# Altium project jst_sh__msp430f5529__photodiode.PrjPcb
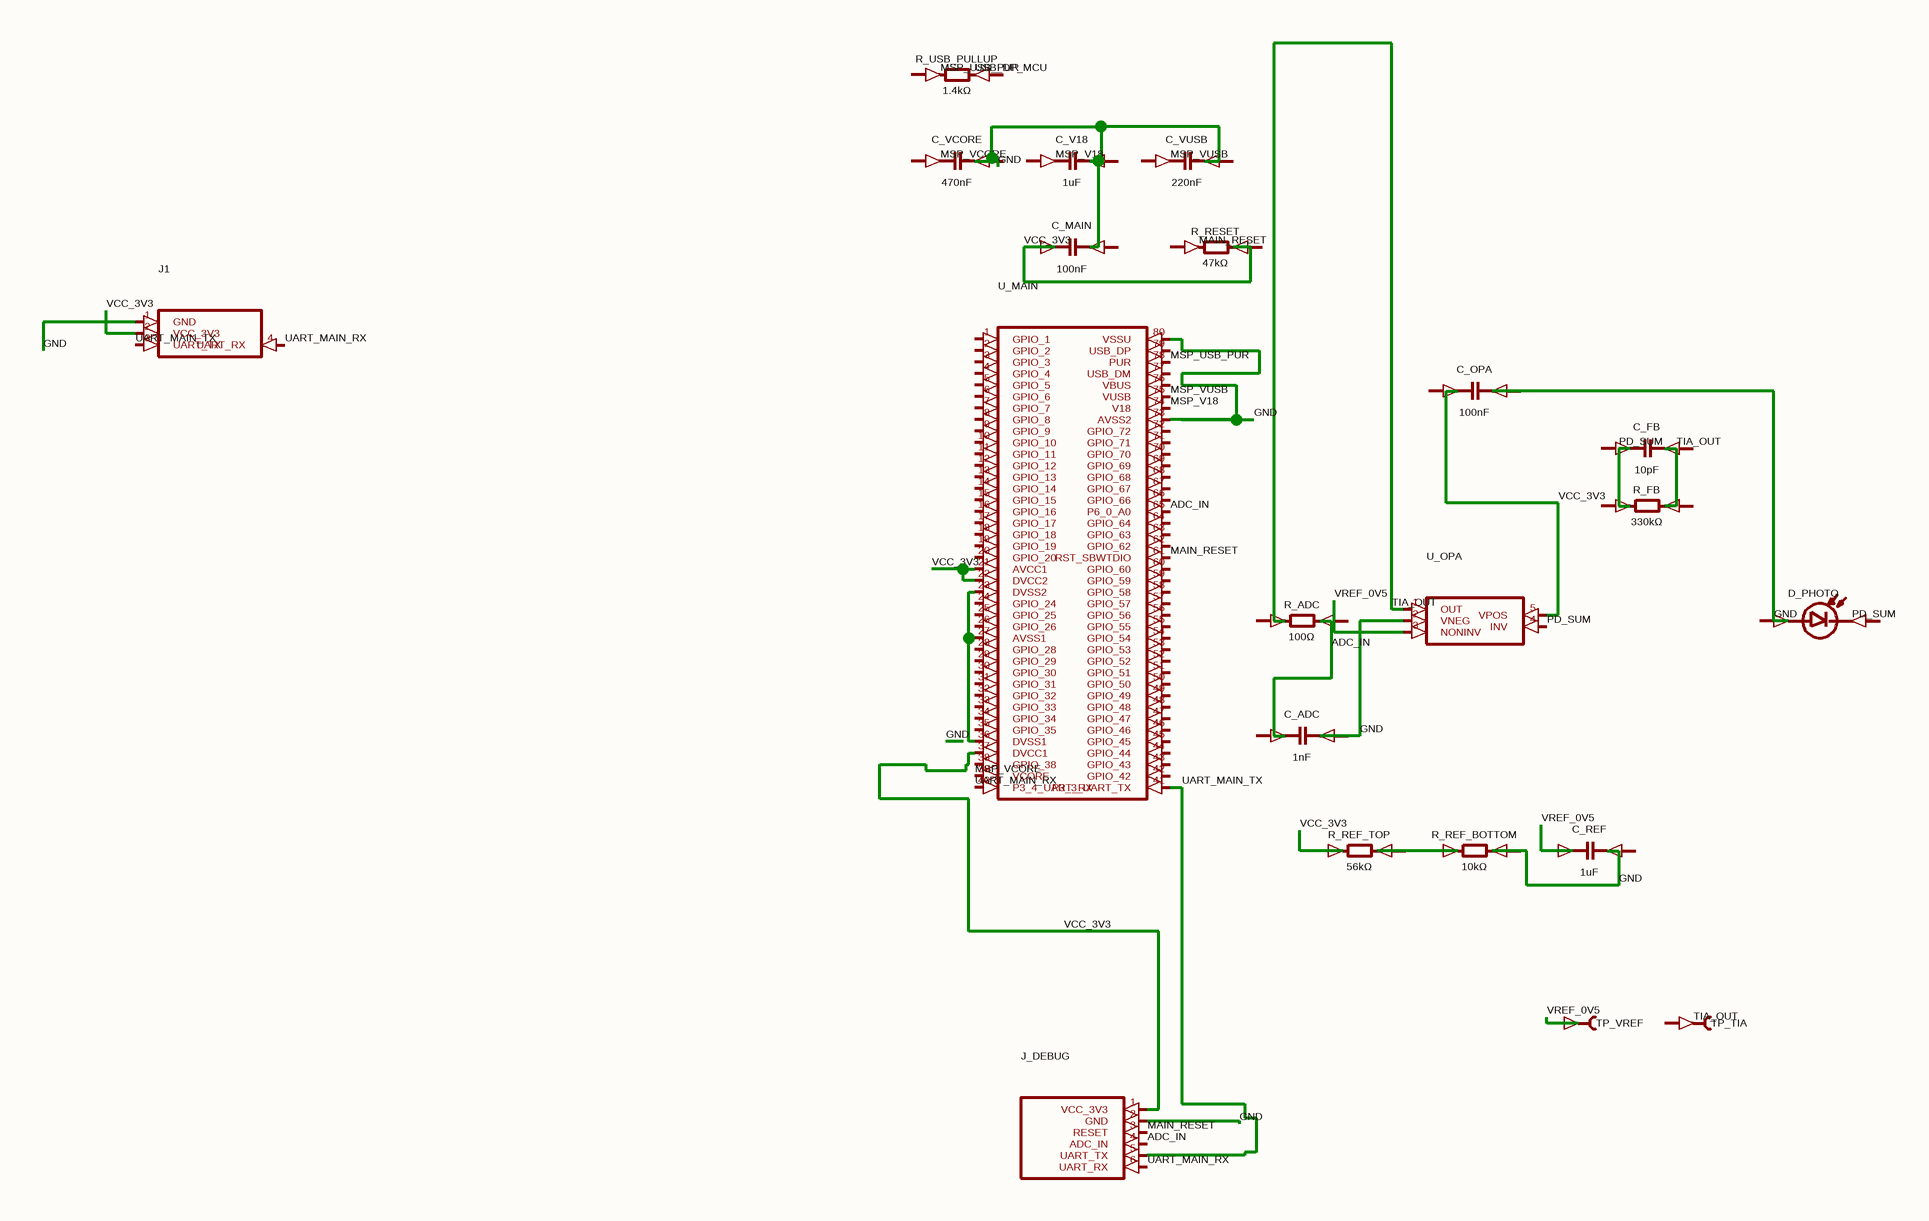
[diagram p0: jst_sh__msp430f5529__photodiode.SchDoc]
1 sheet, 21 parts. Net scope: global (net labels, ports and power ports of the same name join across sheets).
Board file: jst_sh__msp430f5529__photodiode.PcbDoc

## Sheet jst_sh__msp430f5529__photodiode.SchDoc
size 212 x 150 mm

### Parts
C_ADC  1nF
C_FB  10pF
C_MAIN  100nF
C_OPA  100nF
C_REF  1uF
C_V18  1uF
C_VCORE  470nF
C_VUSB  220nF
D_PHOTO  (no value)
J1  (no value)
J_DEBUG  (no value)
R_ADC  100Ω
R_FB  330kΩ
R_REF_BOTTOM  10kΩ
R_REF_TOP  56kΩ
R_RESET  47kΩ
R_USB_PULLUP  1.4kΩ
TP_TIA  (no value)
TP_VREF  (no value)
U_MAIN  (no value)
U_OPA  (no value)

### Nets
ADC_IN: J_DEBUG.4(ADC_IN) U_MAIN.65(P6_0_A0)
GND: C_ADC.2(neg) C_OPA.2(neg) C_REF.1(pos) J1.1(GND) J_DEBUG.2(GND) R_REF_BOTTOM.2(cathode) TP_VREF.1(pin1) U_MAIN.73(AVSS2) U_MAIN.80(VSSU) U_OPA.2(VNEG) U_OPA.3(NONINV)  [also labelled VREF_0V5]
MAIN_RESET: J_DEBUG.3(RESET) U_MAIN.61(RST_SBWTDIO)
MSP_USB_PUR: U_MAIN.78(PUR)
MSP_V18: U_MAIN.74(V18)
MSP_VCORE: U_MAIN.39(VCORE)
MSP_VUSB: U_MAIN.75(VUSB)
PD_SUM: U_OPA.4(INV)
TIA_OUT: U_OPA.1(OUT)
UART_MAIN_RX: J1.4(UART_RX) J_DEBUG.6(UART_RX) U_MAIN.40(P3_4_UART_RX)
UART_MAIN_TX: J1.3(UART_TX) J_DEBUG.5(UART_TX) U_MAIN.41(P3_3_UART_TX)
VCC_3V3: C_MAIN.1(pos) J1.2(VCC_3V3) J_DEBUG.1(VCC_3V3) R_REF_TOP.1(anode) U_MAIN.21(AVCC1) U_MAIN.22(DVCC2) U_MAIN.37(DVCC1) U_OPA.5(VPOS)
NetR_REF_BOTTOM_1: R_REF_BOTTOM.1(anode) R_REF_TOP.2(cathode)
NetU_MAIN_23: U_MAIN.23(DVSS2) U_MAIN.27(AVSS1) U_MAIN.36(DVSS1)

Not connected (* = marked no-connect by the designer): C_ADC 1(pos); C_FB 1(pos) 2(neg); C_MAIN 2(neg); C_OPA 1(pos); C_REF 2(neg); C_V18 1(pos) 2(neg); C_VCORE 1(pos) 2(neg); C_VUSB 1(pos) 2(neg); D_PHOTO 1(anode) 2(cathode); R_ADC 1(anode) 2(cathode); R_FB 1(anode) 2(cathode); R_RESET 1(anode) 2(cathode); R_USB_PULLUP 1(anode) 2(cathode); TP_TIA 1(pin1); U_MAIN 1(GPIO_1) 2(GPIO_2) 3(GPIO_3) 4(GPIO_4) 5(GPIO_5) 6(GPIO_6) 7(GPIO_7) 8(GPIO_8) 9(GPIO_9) 10(GPIO_10) 11(GPIO_11) 12(GPIO_12) 13(GPIO_13) 14(GPIO_14) 15(GPIO_15) 16(GPIO_16) 17(GPIO_17) 18(GPIO_18) 19(GPIO_19) 20(GPIO_20) 24(GPIO_24) 25(GPIO_25) 26(GPIO_26) 28(GPIO_28) 29(GPIO_29) 30(GPIO_30) 31(GPIO_31) 32(GPIO_32) 33(GPIO_33) 34(GPIO_34) 35(GPIO_35) 38(GPIO_38) 42(GPIO_42) 43(GPIO_43) 44(GPIO_44) 45(GPIO_45) 46(GPIO_46) 47(GPIO_47) 48(GPIO_48) 49(GPIO_49) 50(GPIO_50) 51(GPIO_51) 52(GPIO_52) 53(GPIO_53) 54(GPIO_54) 55(GPIO_55) 56(GPIO_56) 57(GPIO_57) 58(GPIO_58) 59(GPIO_59) 60(GPIO_60) 62(GPIO_62) 63(GPIO_63) 64(GPIO_64) 66(GPIO_66) 67(GPIO_67) 68(GPIO_68) 69(GPIO_69) 70(GPIO_70) 71(GPIO_71) 72(GPIO_72) 76(VBUS) 77(USB_DM) 79(USB_DP)

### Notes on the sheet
- Labels drawn without touching a wire or pin: MAIN_RESET, MSP_USB_PUR, MSP_V18, MSP_VCORE, MSP_VUSB, PD_SUM, TIA_OUT, USB_DP_MCU

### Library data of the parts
C_ADC C_FB C_MAIN C_OPA C_REF C_V18 C_VCORE C_VUSB = capacitor_right
D_PHOTO = photodiode_horz
J1 = J1
J_DEBUG = J_DEBUG
R_ADC R_FB R_REF_BOTTOM R_REF_TOP R_RESET R_USB_PULLUP = boxresistor_right
TP_TIA TP_VREF = testpoint_right
U_MAIN = U_MAIN
U_OPA = U_OPA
